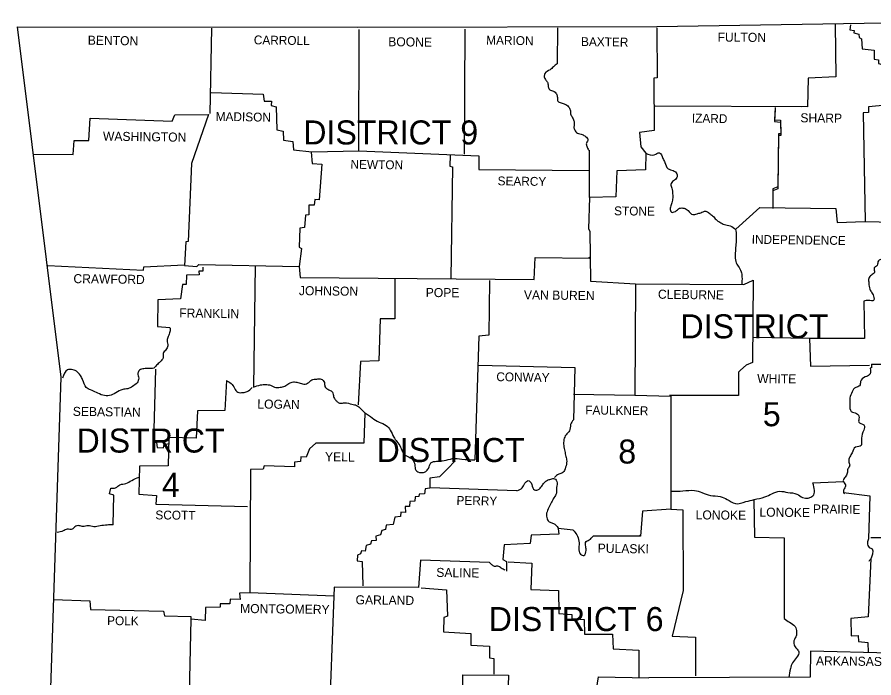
# Model space of a CAD drawing. Extents: x -42408 to 34530, y -43140 to 20491.
# Drawn here: x -42304 to -40066, y 18766 to 20491 of the extents above; entities that cross this region are included whole.
import ezdxf

# ---------------------------------------------------------------- set-up
doc = ezdxf.new("R2010")
doc.units = 0
for name, color, linetype in [('1', 7, 'Continuous'), ('2', 7, 'Continuous'), ('3', 7, 'Continuous')]:
    doc.layers.add(name, color=color, linetype=linetype)

msp = doc.modelspace()

# ---------------------------------------------------------------- linework, layer by layer
at = {"layer": '1'}
for q in [(-40007.3, 19584.6), (-40072.8, 19575.3)]:
    msp.add_line((-40072.8, 19584.6), q, dxfattribs=at)
for points in [[(-42304, 20465.7), (-41414, 20465.2), (-40633.1, 20466.8), (-39711.8, 20481.1), (-39284.7, 20491.1)], [(-42304, 20465.7), (-42190, 19551), (-42239.6, 18057.9)], [(-41796, 20462.4), (-41800.9, 20239.5)], [(-41797.1, 20294), (-41661.7, 20289.6), (-41658.4, 20272), (-41639.7, 20271.5), (-41640.2, 20260.5), (-41627, 20257.2), (-41625.9, 20197.2), (-41608.9, 20193.3), (-41607.8, 20169.6), (-41583.5, 20166.3), (-41582.4, 20144.3), (-41534.6, 20139.4), (-41411.3, 20142.1), (-41410.2, 20458.6)], [(-41134.5, 20459.7), (-41136.1, 20132.8)], [(-40892.3, 20463.5), (-40893.4, 20369.4)], [(-40633.1, 20463.5), (-40632, 20332.6), (-40641.3, 20332), (-40639.7, 20195), (-40678.2, 20189.5), (-40674.9, 20152.6), (-40661.7, 20135.5), (-40662.8, 20092), (-40737.6, 20089.3), (-40740.4, 20022.2), (-40808.6, 20019.9), (-40811.9, 19938.5), (-40808.1, 19931.9), (-40806.4, 19802), (-40688.7, 19794.3), (-40690.3, 19504.3), (-40596.8, 19501.5), (-40596.8, 19206.5), (-40670.5, 19201), (-40676, 19136.1), (-40799.8, 19135.5)], [(-40166.9, 20471.8), (-40165.8, 20335.3), (-40237.4, 20331.4), (-40239.6, 20256.6), (-40637.5, 20258.8)], [(-40127.3, 20471.2), (-40129, 20458), (-40118, 20456.4), (-40118.5, 20449.8), (-40105.8, 20447), (-40104.7, 20438.2), (-40098.7, 20434.4), (-40097, 20407.9), (-40065.7, 20404.6), (-40065.7, 20381), (-40054.1, 20379.3), (-40054.1, 20370), (-40044.2, 20367.2), (-40044.8, 20335.3), (-40035.9, 20333.7), (-40033.7, 20261.6), (-40080.5, 20257.2), (-40080, 20241.7), (-40094.3, 20241.2), (-40089.3, 19957.2), (-39867.5, 19952.3), (-39863.7, 19510.9), (-40008.4, 19507), (-40011.2, 19581.3)], [(-40324.3, 20255), (-40325.4, 20223), (-40310, 20221.9), (-40309.5, 20186.7), (-40315, 20186.7), (-40317.2, 20048), (-40329.8, 20042.5), (-40329.8, 19996.3)], [(-40255.5, 20253.9), (-40255, 20254.4)], [(-42260.5, 20132.8), (-42157.6, 20132.2), (-42154.8, 20168.5), (-42116.8, 20168.5), (-42113.5, 20227.4), (-41898.9, 20219.7), (-41892.3, 20236.2), (-41803.7, 20236.8), (-41848.3, 20109.1), (-41857.1, 19904.9), (-41863.7, 19904.4), (-41867, 19842.7), (-41834.5, 19840), (-41829.6, 19844.9), (-41567, 19840), (-41564.3, 19810.8)], [(-40324.3, 20250), (-40325.4, 20218.1), (-40310, 20217), (-40309.5, 20181.8), (-40315, 20181.8), (-40317.2, 20043.1), (-40329.8, 20037.6), (-40329.8, 19991.3)], [(-41411.3, 20142.1), (-41097.6, 20128.9), (-41098.1, 20093.1), (-40810.3, 20090.9)], [(-40808.6, 20019.9), (-40809.2, 20143.8)], [(-41535.7, 20138.3), (-41533.5, 20108.6), (-41508.1, 20106.9), (-41514.7, 20014.4), (-41526.3, 20015), (-41528.5, 20000.1), (-41541.7, 20000.1), (-41542.3, 19974.8), (-41550.5, 19974.3), (-41553.3, 19941.8), (-41565.4, 19940.1), (-41567, 19890.6), (-41561.5, 19886.8), (-41567, 19840)], [(-41173, 20130.6), (-41173.5, 20102), (-41166.4, 20100.3), (-41170.8, 19809.7)], [(-40426.7, 19937.4), (-40364, 19994.1), (-40165.8, 19991.3), (-40162, 19954.5), (-40089.9, 19957.2)], [(-41564.3, 19810.8), (-40953.4, 19805.9), (-40950.6, 19863.6), (-40808.6, 19862)], [(-40810.3, 19862.5), (-40808.6, 19864.2)], [(-42224.2, 19842.2), (-41973.7, 19830.6), (-41972.6, 19839.4), (-41868.1, 19844.4)], [(-41818.5, 19837.8), (-41818.5, 19827.9), (-41829, 19827.9), (-41828.5, 19818), (-41862, 19817.4), (-41862.6, 19792.7), (-41871.9, 19792.7), (-41876.9, 19755.8), (-41936.3, 19753), (-41936.9, 19683.1), (-41904.9, 19680.9)], [(-41682.6, 19842.2), (-41686.5, 19524.6)], [(-41317.2, 19806.4), (-41317.7, 19703.5), (-41355.7, 19702.9), (-41359, 19593.4), (-41407.4, 19591.8), (-41412.9, 19478.4)], [(-40688.7, 19794.3), (-40405.8, 19792.7), (-40381.6, 19804.2), (-40383.2, 19589), (-40399.7, 19581.9), (-40414.6, 19569.2), (-40419.5, 19564.3), (-40420.1, 19502.6), (-40600.1, 19502.6)], [(-41070.6, 19803.7), (-41071.7, 19660.6), (-41098.1, 19658.4), (-41108.6, 19334.8)], [(-40092.1, 19749.2), (-40091, 19652.3), (-40234.1, 19651.8), (-40381, 19654.5)], [(-40234.1, 19651.8), (-40231.9, 19579.7), (-40077.2, 19582.4)], [(-41099.2, 19581.9), (-40847.7, 19575.8), (-40851, 19439.9)], [(-41942.4, 19572), (-41947.9, 19382.6), (-41939.6, 19380.4), (-41938, 19367.2), (-41921.5, 19366.1), (-41919.8, 19375.5), (-41906.6, 19377.7)], [(-40072.8, 19575.3), (-40075.6, 19574.7)], [(-41757.5, 19542.2), (-41761.3, 19463.5), (-41832.9, 19463), (-41836.7, 19391.4), (-41907.7, 19393.1), (-41909.9, 19319.3), (-41984.2, 19318.8), (-41986.4, 19245.1), (-41939.6, 19242.3), (-41941.3, 19219.7), (-41702.4, 19213.1)], [(-40850.5, 19506.5), (-40690.3, 19504.3)], [(-39863.6, 19508.1), (-39855.4, 19209.3), (-39986.4, 19208.7), (-39987, 19196.6), (-40024.9, 19194.4), (-40028.2, 19131.7), (-40074.5, 19131.7)], [(-41395.9, 19458), (-41398.1, 19378.8), (-41523.6, 19378.2), (-41540.1, 19363.9), (-41549.4, 19341.9), (-41563.2, 19343), (-41563.7, 19330.4), (-41579.7, 19328.7), (-41579.1, 19317.1), (-41658.9, 19319.3), (-41661.7, 19310.5), (-41694.7, 19309.4), (-41695.8, 18987.5), (-41723.3, 18986.9), (-41721.1, 18970.4), (-41747.5, 18971), (-41748.1, 18958.9), (-41774, 18958.9), (-41773.4, 18950.1), (-41811.9, 18949), (-41812.5, 18915.4), (-41849.9, 18918.7), (-41856, 18647.9)], [(-41159.8, 19332.6), (-41179.6, 19311.1), (-41201, 19290.7), (-41225.8, 19286.9), (-41225.8, 19261), (-41237.9, 19259.4), (-41240.1, 19246.2), (-41253.9, 19245.1), (-41255, 19239), (-41264.3, 19238.4), (-41264.9, 19226.9), (-41278.1, 19226.3), (-41279.2, 19213.1), (-41290.2, 19213.1), (-41289.7, 19197.7), (-41301.8, 19198.8), (-41302.3, 19186.7), (-41317.2, 19185.6), (-41321.6, 19165.8), (-41340.3, 19164.1), (-41341.9, 19153.1), (-41351.8, 19150.4), (-41354.6, 19138.8), (-41367.3, 19136.1), (-41366.2, 19124.5), (-41378.8, 19123.4), (-41381, 19114.6), (-41392.6, 19111.3), (-41395.3, 19096.5), (-41404.1, 19097), (-41406.9, 19089.3), (-41415.1, 19086.5), (-41415.7, 19071.7), (-41403, 19069.5), (-41400.8, 19005.6)], [(-40225.3, 19274.8), (-40145.5, 19278.6)], [(-42053, 19165.3), (-42051.3, 19242.9), (-42062.4, 19246.2), (-42059, 19261)], [(-40998.5, 19254.4), (-41225.3, 19261.6)], [(-40145.5, 19250), (-40076.7, 19241.2), (-40080.5, 19128.9)], [(-40379.4, 19231.8), (-40378.3, 19133.3), (-40300.7, 19131.7), (-40300.1, 18920.3)], [(-40596.8, 19206.5), (-40564.8, 19204.3), (-40564.3, 18994.1), (-40592.9, 18874.7), (-40531.8, 18871.9), (-40532.4, 18770.6)], [(-40851.6, 19151.5), (-40891.2, 19155.9), (-40889.5, 19141), (-40961.6, 19138.3), (-40963.8, 19116.8), (-41031.5, 19113), (-41035.4, 19074.4), (-41025.5, 19069.5), (-41025.5, 19044.2)], [(-40678.8, 19136.6), (-40676, 19139.4)], [(-41070.6, 19067.3), (-41250.6, 19072.8), (-41255.5, 19001.8), (-41475.7, 19002.9), (-41476.8, 18979.2)], [(-41021.6, 19068.9), (-40960, 19065.1), (-40962.2, 18996.3), (-40890.1, 18993.5), (-40889, 18933.6), (-40854.9, 18930.8), (-40854.9, 18920.3), (-40823, 18918.1), (-40821.9, 18879.6), (-40749.2, 18879.6), (-40747, 18841.6), (-40679.9, 18838.3), (-40680.4, 18766.8)], [(-40074.5, 19076.1), (-40081.1, 18925.3), (-40126.2, 18920.3), (-40125.1, 18875.8), (-40106.9, 18876.3), (-40106.4, 18860.9), (-40081.6, 18858.2), (-40080.8, 18831.6)], [(-41248.9, 19000.7), (-41182.3, 18995.7), (-41180.1, 18926.4), (-41189.5, 18923.1), (-41190.6, 18886.2), (-41118.5, 18881.3), (-41118.5, 18851), (-41070.6, 18848.2), (-41070.1, 18818), (-41058.5, 18816.3), (-41059.1, 18775.6)], [(-41476.8, 18979.2), (-41695.8, 18987.5)], [(-41476.8, 18979.2), (-41489.4, 18636.4)], [(-42209.3, 18970.4), (-42114.1, 18967.1), (-42111.9, 18944), (-41921.5, 18940.2), (-41919.3, 18928), (-41849.9, 18925.8), (-41850.5, 18915.4)], [(-40023.8, 18830.1), (-40231.9, 18835.6), (-40233, 18767.9), (-40654, 18766.2)], [(-41485.6, 18682), (-41170.8, 18677.6), (-41164.7, 18729.9), (-41140, 18729.9), (-41139.4, 18773.9), (-41020.5, 18772.3), (-41021.6, 18745.9), (-40990.8, 18743.7), (-40990.8, 18695.2), (-40971, 18693.6)], [(-40971, 18693.6), (-40940.2, 18698), (-40938, 18716.7), (-40919.8, 18720), (-40918.7, 18731), (-40790.5, 18734.9), (-40785.5, 18768.4), (-40654, 18766.2)]]:
    msp.add_lwpolyline(points, dxfattribs=at)
for points in [[(-40893.4, 20369.4), (-40903.3, 20361.2), (-40912.1, 20353.5), (-40925.3, 20344.1), (-40927, 20335.3), (-40922.6, 20326.5), (-40918.2, 20319.3), (-40916.5, 20309.4), (-40912.7, 20301.2), (-40903.3, 20297.9), (-40895.6, 20290.7), (-40892.8, 20280.8), (-40891.7, 20271.5), (-40882.9, 20267.1), (-40873, 20263.8), (-40863.7, 20257.2), (-40859.3, 20248.9), (-40858.2, 20238.4), (-40854.3, 20230.2), (-40849.9, 20220.3), (-40848.8, 20212), (-40849.9, 20203.8), (-40847.7, 20196.1), (-40840.6, 20188.4), (-40827.9, 20184.5), (-40819.1, 20179), (-40813, 20171.3), (-40816.9, 20161.9), (-40816.3, 20153.7), (-40811.4, 20143.8)], [(-40661.7, 20135.5), (-40639.7, 20131.7), (-40626.5, 20136.6), (-40617.1, 20122.3), (-40612.2, 20111.3), (-40603.9, 20095.3), (-40590.7, 20090.4), (-40580.8, 20081.6), (-40580.8, 20072.2), (-40589.6, 20063.4), (-40596.2, 20054.6), (-40594, 20044.2), (-40591.8, 20029.9), (-40591.8, 20016.1), (-40595.1, 20003.4), (-40597.9, 19991.9), (-40595.1, 19982), (-40584.7, 19983.6), (-40573.6, 19991.9), (-40562.1, 19991.9), (-40551.1, 19985.8), (-40539.5, 19975.4), (-40528, 19977.6), (-40518.6, 19980.3), (-40505.4, 19984.2), (-40496, 19979.2), (-40487.8, 19972.6), (-40477.9, 19962.2), (-40468.5, 19955.6), (-40456.4, 19949.5), (-40441.6, 19945.7), (-40427.8, 19936.3), (-40425.6, 19920.3), (-40426.1, 19906.6), (-40427.2, 19889.5), (-40428.4, 19870.8), (-40426.7, 19852.6), (-40420.6, 19840.5), (-40412.9, 19826.2), (-40410.7, 19813), (-40411.3, 19792.1)], [(-39993.6, 19947.3), (-40000.2, 19930.2), (-40007.9, 19913.7), (-40012.8, 19899.4), (-40023.3, 19891.2), (-40026.6, 19883.5), (-40035.9, 19880.2), (-40043.1, 19869.2), (-40046.4, 19859.2), (-40054.1, 19854.8), (-40058, 19842.7), (-40065.1, 19836.1), (-40064.6, 19825.1), (-40072.8, 19817.4), (-40079.4, 19808.6), (-40079.4, 19796.5), (-40076.7, 19780.5), (-40071.2, 19771.2), (-40066.2, 19759.1), (-40066.8, 19751.4), (-40080.5, 19751.4), (-40092.1, 19749.2)], [(-41904.9, 19680.9), (-41904.9, 19669.4), (-41909.4, 19657.3), (-41912.1, 19646.8), (-41910.5, 19633.1), (-41915.4, 19622), (-41922.6, 19613.2), (-41922.6, 19602.2), (-41930.8, 19590.7), (-41939.6, 19581.9), (-41947.3, 19574.7), (-41961.1, 19573.6), (-41972.6, 19573.1), (-41984.2, 19569.2), (-41988.6, 19561), (-41986.4, 19548.3), (-41990.8, 19536.2), (-42002.4, 19526.8), (-42015, 19520.8), (-42028.2, 19518.6), (-42046.4, 19509.8), (-42062.9, 19502.6), (-42080.5, 19503.7), (-42097, 19510.9), (-42111.9, 19517.5), (-42123.4, 19524.1), (-42132.8, 19544.4), (-42138.8, 19555.5), (-42149.3, 19566.5), (-42162, 19570.9), (-42172.4, 19569.8), (-42185.1, 19548.3)], [(-40075.6, 19574.7), (-40078.3, 19556.6), (-40088.8, 19551.6), (-40100.9, 19539.5), (-40103.6, 19528.5), (-40113.5, 19524.1), (-40122.9, 19512.5), (-40129, 19496.6), (-40129, 19480.1), (-40125.1, 19461.3), (-40111.3, 19456.4), (-40104.7, 19445.4), (-40105.8, 19433.8), (-40092.6, 19426.1), (-40090.4, 19419.5), (-40092.6, 19412.4), (-40098.7, 19392), (-40098.1, 19378.2), (-40099.2, 19372.2), (-40114.1, 19368.3), (-40122.9, 19353.5), (-40129, 19343), (-40131.2, 19329.3), (-40129.5, 19319.3), (-40133.9, 19311.6), (-40135.6, 19300.1), (-40141.1, 19290.2), (-40146, 19280.8), (-40140.5, 19269.8), (-40142.2, 19262.1), (-40145.5, 19250), (-40142.7, 19246.2)], [(-41757.5, 19542.2), (-41745.3, 19534.5), (-41736, 19521.9), (-41727.7, 19511.4), (-41714, 19510.9), (-41703, 19513.1), (-41690.3, 19524.1)], [(-41686.5, 19524.6), (-41668.3, 19530.7), (-41655.1, 19531.8), (-41641.9, 19529.6), (-41628.1, 19524.1), (-41613.3, 19525.2), (-41602.3, 19529), (-41591.2, 19536.2), (-41579.1, 19538.4), (-41567.6, 19536.2), (-41555.5, 19532.9), (-41542.3, 19536.7), (-41534.6, 19543.9), (-41521.4, 19546.1), (-41509.8, 19546.1), (-41501.5, 19536.7), (-41499.9, 19526.8), (-41489.4, 19517.5), (-41480.1, 19511.4), (-41477.3, 19499.9), (-41472.4, 19491.6), (-41467.4, 19486.1), (-41460.3, 19482.8), (-41448.2, 19483.9), (-41429.4, 19480.1), (-41417.3, 19477.3), (-41406.3, 19467.9), (-41395.9, 19458)], [(-41395.9, 19458), (-41376.6, 19444.8), (-41358.4, 19433.3), (-41339.7, 19425), (-41329.3, 19412.9), (-41319.9, 19394.2), (-41312.2, 19382.6), (-41302.3, 19368.3), (-41295.2, 19352.4), (-41283.6, 19343.6), (-41271.5, 19335.9), (-41265.4, 19322.1), (-41262.7, 19308.3), (-41249.5, 19301.7), (-41236.8, 19304.5), (-41229.7, 19312.7), (-41223.1, 19327.1), (-41208.2, 19331.5), (-41188.9, 19333.1), (-41166.9, 19338.1), (-41142.7, 19337), (-41108.6, 19334.8)], [(-40851, 19439.9), (-40858.2, 19427.2), (-40861.5, 19410.7), (-40870.3, 19400.3), (-40875.8, 19388.1), (-40876.3, 19372.2), (-40873.6, 19357.9), (-40870.8, 19344.1), (-40868.6, 19331.5), (-40871.4, 19315.5), (-40878.5, 19301.7), (-40889.5, 19297.9), (-40900, 19288.5)], [(-42059, 19261), (-42046.9, 19262.1), (-42035.4, 19269.8), (-42020, 19273.1), (-42004.6, 19281.4), (-41985.3, 19290.2)], [(-40998.5, 19254.4), (-40984.8, 19262.1), (-40977.6, 19273.7), (-40968.8, 19280.8), (-40960, 19270.9), (-40952.3, 19256.6), (-40944, 19256.6), (-40933.6, 19266.5), (-40927, 19275.3), (-40918.7, 19281.9), (-40909.9, 19284.7), (-40900.6, 19285.8), (-40893.4, 19275.3), (-40895.6, 19258.8), (-40895.6, 19247.8), (-40901.7, 19236.2), (-40908.3, 19224.1), (-40915.4, 19210.4), (-40920.9, 19195.5), (-40919.8, 19181.2), (-40912.1, 19171.9), (-40903.3, 19169.1), (-40891.2, 19157)], [(-40595.7, 19252.8), (-40564.8, 19253.9), (-40534.6, 19255), (-40515.3, 19249.5), (-40493.3, 19242.3), (-40467.4, 19239), (-40449.3, 19231.8), (-40427.8, 19220.8), (-40400.3, 19225.8), (-40378.8, 19231.3), (-40350.8, 19238.4), (-40332.6, 19246.2), (-40311.7, 19252.8), (-40290.8, 19250), (-40267.1, 19245.6), (-40252.2, 19236.8), (-40225.3, 19240.6), (-40225.3, 19274.8)], [(-42053, 19165.3), (-42069, 19164.7), (-42087.1, 19162.5), (-42103.6, 19160.3), (-42118.5, 19163), (-42132.2, 19160.8), (-42141.6, 19163), (-42153.2, 19160.3), (-42159.8, 19153.7), (-42173.5, 19153.7), (-42183.4, 19149.3), (-42199.4, 19145.4)], [(-40851.6, 19151.5), (-40842.2, 19139.4), (-40836.7, 19122.9), (-40836.7, 19104.2), (-40832.3, 19088.8), (-40823.5, 19085.4), (-40818, 19098.7), (-40819.1, 19111.9), (-40819.1, 19119.6), (-40809.7, 19126.2), (-40799.8, 19135.5)], [(-40080.5, 19128.9), (-40082.7, 19117.9), (-40078.3, 19106.4), (-40070.6, 19102.5), (-40069.5, 19091.5), (-40072.3, 19080.5), (-40074.5, 19076.1), (-40079.4, 19069.5)], [(-41029.3, 19046.9), (-41039.8, 19052.4), (-41048, 19057.4), (-41056.9, 19056.8), (-41064, 19061.2), (-41070.6, 19067.3)], [(-40300.1, 18920.3), (-40286.4, 18911), (-40272, 18900), (-40268.2, 18885.1), (-40269.3, 18874.7), (-40273.7, 18865.9), (-40274.8, 18852.1), (-40268.2, 18842.2), (-40262.1, 18833.9), (-40268.2, 18819.1), (-40278.7, 18805.3), (-40284.2, 18789.9), (-40288, 18766.8)]]:
    msp.add_spline(points, degree=3, dxfattribs=at)

# ---------------------------------------------------------------- texts
at = {"layer": '2'}
for s, height, rotation, p in [('BENTON', 23.67, 359.2527, (-42119.6, 20419)), ('CARROLL', 23.11, 359.1481, (-41685.9, 20420.1)), ('BOONE', 23.67, 359.4001, (-41334.8, 20415.1)), ('MARION', 23.11, 359.1854, (-41078.9, 20419.5)), ('BAXTER', 23.11, 359.2559, (-40831.2, 20415.7)), ('FULTON', 23.66, 359.4996, (-40474.6, 20427.2)), ('MADISON', 23.11, 359.0906, (-41785.5, 20220.3)), ('IZARD', 23.11, 358.9258, (-40541.7, 20215.9)), ('SHARP', 23.66, 359.3905, (-40258.3, 20216.4)), ('WASHINGTON', 23.66, 359.232, (-42080, 20168.5)), ('NEWTON', 23.11, 359.2717, (-41433.3, 20095.3)), ('SEARCY', 23.11, 359.2527, (-41049.1, 20051.9)), ('STONE', 23.11, 359.4001, (-40744.8, 19973.7)), ('INDEPENDENCE', 23.108, 359.2187, (-40385.4, 19899.4)), ('CRAWFORD', 23.66, 359.2771, (-42157, 19796.5)), ('JOHNSON', 23.67, 359.3514, (-41568.1, 19765.1)), ('POPE', 23.67, 359.6155, (-41236.8, 19760.2)), ('VAN BUREN', 23.67, 359.3508, (-40980.4, 19754.1)), ('CLEBURNE', 23.66, 359.2535, (-40630.3, 19755.8)), ('FRANKLIN', 23.67, 359.1815, (-41880.7, 19706.8)), ('CONWAY', 23.11, 359.0371, (-41052.5, 19540.6)), ('WHITE', 23.67, 359.3139, (-40371.1, 19535.6)), ('LOGAN', 23.67, 359.3969, (-41676.6, 19469)), ('SEBASTIAN', 23.66, 359.2816, (-42158.7, 19449.8)), ('FAULKNER', 23.11, 359.2486, (-40820.2, 19453.6)), ('YELL', 23.67, 359.1987, (-41499.9, 19331.5)), ('PERRY', 23.11, 359.0858, (-41156.5, 19217.5)), ('SCOTT', 23.11, 359.4063, (-41942.9, 19179.6)), ('LONOKE', 23.67, 359.4974, (-40531.8, 19179.6)), ('LONOKE', 23.67, 359.4974, (-40365.1, 19186.7)), ('PRAIRIE', 23.11, 359.2116, (-40225.3, 19195.5)), ('PULASKI', 23.67, 359.053, (-40787.7, 19092.6)), ('SALINE', 23.67, 359.1491, (-41209.3, 19029.3)), ('GARLAND', 23.67, 359.3658, (-41420.1, 18957.8)), ('MONTGOMERY', 23.67, 359.2944, (-41721.7, 18935.2)), ('POLK', 23.11, 359.2152, (-42069, 18903.8)), ('ARKANSAS', 23.66, 359.2678, (-40217.6, 18798.7))]:
    msp.add_text(s, height=height, rotation=rotation, dxfattribs=at).set_placement(p)
at = {"layer": '3'}
for s, height, p in [('DISTRICT 9', 62.74, (-41556.6, 20158.6)), ('DISTRICT', 62.74, (-40571.4, 19652.3)), ('5', 62.7, (-40356.3, 19422.8)), ('DISTRICT', 62.74, (-42148.8, 19354)), ('DISTRICT', 62.74, (-41365.1, 19329.3)), ('8', 62.7, (-40733.8, 19325.4)), ('4', 62.7, (-41925.9, 19238.4)), ('DISTRICT 6', 62.74, (-41072.3, 18887.9))]:
    msp.add_text(s, height=height, dxfattribs=at).set_placement(p)

doc.saveas('drawing.dxf')
